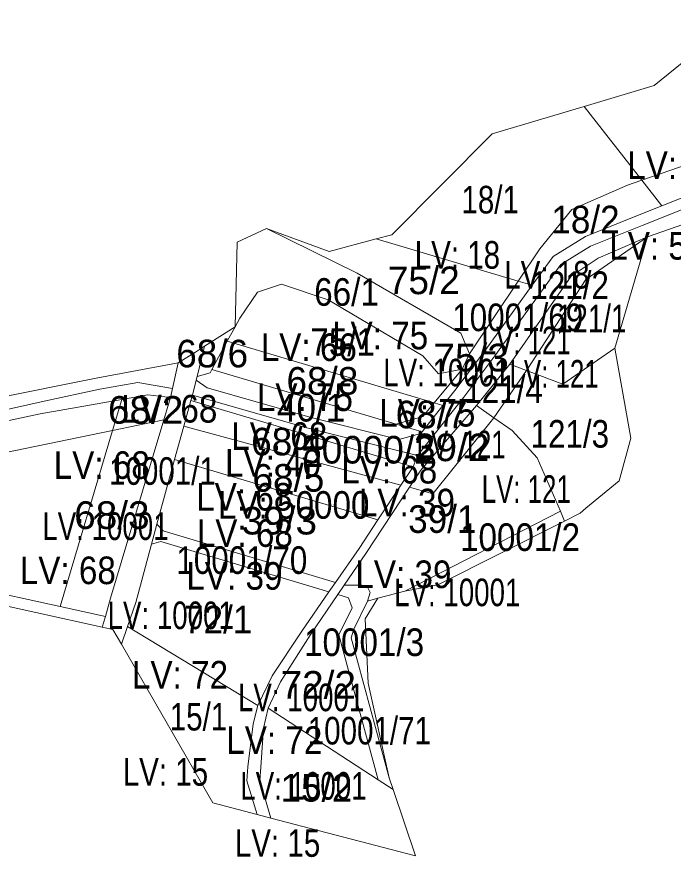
# Model space of a CAD drawing. Extents: x -713758 to -711119, y -1123067 to -1120789.
# Drawn here: x -713406.4 to -713168.6, y -1122325.9 to -1122021.5 of the extents above; entities that cross this region are included whole.
import ezdxf
from ezdxf.enums import TextEntityAlignment as Align

# ---------------------------------------------------------------- set-up
doc = ezdxf.new("R2010")
doc.units = 0
doc.header["$LTSCALE"] = 4
doc.layers.add('10', color=7, linetype='Continuous', lineweight=13)
doc.layers.add('11', color=7, linetype='Continuous')
doc.layers.add('13', color=7, linetype='Continuous')

msp = doc.modelspace()

# ---------------------------------------------------------------- linework, layer by layer
at = {"layer": '10'}
for points in [[(-713200.85, -1122053.94), (-713175.48, -1122046.35), (-713162.84, -1122036.08), (-713160.35, -1122039.4), (-713146.75, -1122034.59), (-713141.44, -1122029.61), (-713138.12, -1122034.76), (-713130.99, -1122030.94), (-713130.49, -1122024.8), (-713126.01, -1122031.6), (-713119.7, -1122021.46), (-713099.09, -1122050.28), (-713107.42, -1122053.38), (-713135.98, -1122065.38), (-713179.96, -1122080.66)], [(-713179.96, -1122080.66), (-713172.8, -1122089.95), (-713132.6, -1122073.85), (-713103.43, -1122061.72), (-713093.3, -1122058.22), (-713099.09, -1122050.28), (-713107.42, -1122053.38), (-713135.98, -1122065.38)], [(-713276.22, -1122101.91), (-713270.52, -1122100.4), (-713234.17, -1122063.9), (-713200.85, -1122053.94), (-713179.96, -1122080.66), (-713185.22, -1122082.48), (-713205.39, -1122091.27), (-713216.93, -1122105.54), (-713224.76, -1122117.22)], [(-713224.76, -1122117.22), (-713219.72, -1122118.72), (-713212.15, -1122108.25), (-713200.39, -1122101), (-713181.58, -1122093.48), (-713172.8, -1122089.95), (-713179.96, -1122080.66), (-713185.22, -1122082.48), (-713205.39, -1122091.27), (-713216.93, -1122105.54)], [(-713327.34, -1122133.82), (-713325.62, -1122130.68), (-713319.26, -1122121.21), (-713310.46, -1122118.36), (-713293.66, -1122124.01), (-713259.29, -1122144.32), (-713253.7, -1122150.79), (-713245.07, -1122149.07), (-713242.41, -1122143.56), (-713245.61, -1122136.04), (-713283.08, -1122114.33), (-713315.94, -1122098.12), (-713326.63, -1122103.08)], [(-713315.94, -1122098.12), (-713293.3, -1122106.44), (-713276.22, -1122101.91), (-713224.76, -1122117.22), (-713242.41, -1122143.56), (-713245.61, -1122136.04), (-713283.08, -1122114.33)], [(-713227.78, -1122147.31), (-713205.63, -1122115.4), (-713195.81, -1122108.91), (-713177.94, -1122101.13), (-713200.31, -1122116.67), (-713221.71, -1122149.59)], [(-713221.71, -1122149.59), (-713200.31, -1122116.67), (-713177.94, -1122101.13), (-713189.83, -1122141.53), (-713208.63, -1122154.49)], [(-713255.18, -1122161.34), (-713252.02, -1122162.28), (-713247.68, -1122156.81), (-713236.52, -1122141.96), (-713219.72, -1122118.72), (-713224.76, -1122117.22), (-713242.41, -1122143.56), (-713245.07, -1122149.07)], [(-713330.18, -1122139.02), (-713327.34, -1122133.82), (-713325.62, -1122130.68), (-713319.26, -1122121.21), (-713310.46, -1122118.36), (-713293.66, -1122124.01), (-713259.29, -1122144.32), (-713253.7, -1122150.79), (-713245.07, -1122149.07), (-713255.18, -1122161.34)], [(-713341.07, -1122151.74), (-713336.38, -1122150.38), (-713335.74, -1122149.21), (-713330.18, -1122139.02), (-713327.34, -1122133.82), (-713338.36, -1122140.8)], [(-713335.74, -1122149.21), (-713330.18, -1122139.02), (-713255.18, -1122161.34), (-713259.28, -1122166.31), (-713268.96, -1122169.08)], [(-713375.41, -1122242.51), (-713371.58, -1122243.35), (-713368.49, -1122248.72), (-713366.29, -1122242.33), (-713363.3, -1122233.65), (-713357.62, -1122212.53), (-713355.65, -1122205.21), (-713352.22, -1122192.45), (-713349.27, -1122181.82), (-713345.92, -1122169.75), (-713343.34, -1122160.48), (-713342.74, -1122158.5), (-713341.39, -1122153.06), (-713341.07, -1122151.74), (-713338.36, -1122140.8), (-713341.68, -1122142.9), (-713345.35, -1122145.22), (-713347.92, -1122146.85), (-713349.96, -1122156.15), (-713350.67, -1122159.31), (-713353.1, -1122167.47), (-713372.39, -1122232.08), (-713374.3, -1122238.66)], [(-713233.57, -1122166.7), (-713221.71, -1122149.59), (-713208.63, -1122154.49), (-713189.83, -1122141.53), (-713184, -1122174.1), (-713188.25, -1122189.5), (-713200.28, -1122199.51), (-713202.32, -1122201.29), (-713207.97, -1122204.13), (-713209.43, -1122200.56), (-713217.93, -1122181.24), (-713226.99, -1122171.38)], [(-713471.06, -1122176.68), (-713420.3, -1122165.95), (-713396.46, -1122160.64), (-713376.27, -1122156.29), (-713362.5, -1122153.91), (-713349.96, -1122156.15), (-713347.92, -1122146.85), (-713377.62, -1122152.32), (-713415.72, -1122159.97), (-713435.98, -1122165.29), (-713460.95, -1122160.94), (-713469.32, -1122159.14)], [(-713239.89, -1122162.21), (-713227.78, -1122147.31), (-713221.71, -1122149.59), (-713233.57, -1122166.7)], [(-713341.39, -1122153.06), (-713337.48, -1122155.85), (-713299.82, -1122166.66), (-713267.97, -1122174.55), (-713260.03, -1122172.37), (-713259.62, -1122171.86), (-713268.96, -1122169.08), (-713335.74, -1122149.21), (-713336.38, -1122150.38), (-713341.07, -1122151.74)], [(-713472.83, -1122194.45), (-713411, -1122179.39), (-713371.73, -1122171.3), (-713368.39, -1122160.09), (-713397.9, -1122165.24), (-713456.26, -1122177.73), (-713471.45, -1122180.61)], [(-713371.73, -1122171.3), (-713353.1, -1122167.47), (-713350.67, -1122159.31), (-713358.93, -1122158.44), (-713368.39, -1122160.09)], [(-713345.92, -1122169.75), (-713267.27, -1122191.11), (-713262.86, -1122184.43), (-713301.44, -1122172.89), (-713343.34, -1122160.48)], [(-713343.34, -1122160.48), (-713342.74, -1122158.5), (-713300.85, -1122170.53), (-713261.24, -1122180.34), (-713262.86, -1122184.43), (-713301.44, -1122172.89)], [(-713268.96, -1122169.08), (-713259.28, -1122166.31), (-713255.18, -1122161.34), (-713252.02, -1122162.28), (-713259.62, -1122171.86)], [(-713264.13, -1122191.89), (-713255.71, -1122194.31), (-713233.57, -1122166.7), (-713239.89, -1122162.21), (-713260.06, -1122185.75)], [(-713390.72, -1122235.07), (-713374.3, -1122238.66), (-713372.39, -1122232.08), (-713353.1, -1122167.47), (-713371.73, -1122171.3)], [(-713287.77, -1122227.3), (-713281.4, -1122227.39), (-713279.29, -1122228.27), (-713278.43, -1122230.03), (-713279.35, -1122233.09), (-713275.6, -1122232.08), (-713265.87, -1122229.47), (-713209.43, -1122200.56), (-713217.93, -1122181.24), (-713226.99, -1122171.38), (-713233.57, -1122166.7), (-713255.71, -1122194.31), (-713264.13, -1122191.89), (-713280, -1122215.83)], [(-713475.42, -1122220.51), (-713462.41, -1122220.52), (-713422.85, -1122228.06), (-713390.72, -1122235.07), (-713371.73, -1122171.3), (-713411, -1122179.39), (-713472.83, -1122194.45)], [(-713349.27, -1122181.82), (-713345.92, -1122169.75), (-713267.27, -1122191.11), (-713275.6, -1122203.73)], [(-713355.65, -1122205.21), (-713352.22, -1122192.45), (-713349.27, -1122181.82), (-713275.6, -1122203.73), (-713282.39, -1122214.01), (-713290.95, -1122226.34), (-713353.34, -1122207.63)], [(-713265.87, -1122229.47), (-713253.9, -1122227.22), (-713207.97, -1122204.13), (-713209.43, -1122200.56)], [(-713357.62, -1122212.53), (-713354.25, -1122211.53), (-713293.35, -1122229.79), (-713290.95, -1122226.34), (-713353.34, -1122207.63), (-713355.65, -1122205.21)], [(-713366.29, -1122242.33), (-713319.07, -1122270.98), (-713313.87, -1122260.23), (-713303.19, -1122243.97), (-713293.35, -1122229.79), (-713354.25, -1122211.53), (-713357.62, -1122212.53), (-713363.3, -1122233.65)], [(-713290.11, -1122230.74), (-713286.19, -1122231.92), (-713284.96, -1122235.53), (-713289.71, -1122245.4), (-713275.5, -1122297.87), (-713270.12, -1122301.38), (-713271.56, -1122297.12), (-713285.27, -1122246.48), (-713284.28, -1122243.34), (-713279.35, -1122233.09), (-713278.43, -1122230.03), (-713279.29, -1122228.27), (-713281.4, -1122227.39), (-713287.77, -1122227.3)], [(-713315.35, -1122271.91), (-713275.5, -1122297.87), (-713289.71, -1122245.4), (-713284.96, -1122235.53), (-713286.19, -1122231.92), (-713290.11, -1122230.74), (-713300.12, -1122245.52), (-713310.87, -1122262.42)], [(-713285.27, -1122246.48), (-713271.56, -1122297.12), (-713279.07, -1122262.87), (-713280.16, -1122239.53), (-713275.6, -1122232.08), (-713279.35, -1122233.09), (-713284.28, -1122243.34)], [(-713368.49, -1122248.72), (-713335.41, -1122306.22), (-713319.33, -1122310.43), (-713323.12, -1122298.26), (-713322.68, -1122293.19), (-713320.82, -1122277.56), (-713319.07, -1122270.98), (-713366.29, -1122242.33)], [(-713318.32, -1122298.13), (-713314.36, -1122311.73), (-713261.97, -1122325.43), (-713270.12, -1122301.38), (-713275.5, -1122297.87), (-713315.35, -1122271.91), (-713317.02, -1122279.18), (-713318.04, -1122293.27)]]:
    msp.add_lwpolyline(points, close=True, dxfattribs=at)
for points in [[(-713132.6, -1122073.85), (-713172.8, -1122089.95), (-713181.58, -1122093.48), (-713200.39, -1122101), (-713212.15, -1122108.25), (-713219.72, -1122118.72), (-713236.52, -1122141.96), (-713247.68, -1122156.81), (-713252.02, -1122162.28), (-713259.62, -1122171.86), (-713260.03, -1122172.37), (-713267.97, -1122174.55), (-713299.82, -1122166.66), (-713337.48, -1122155.85), (-713341.39, -1122153.06), (-713342.74, -1122158.5), (-713300.85, -1122170.53), (-713261.24, -1122180.34), (-713244.52, -1122159.26), (-713233.28, -1122144.31), (-713209.37, -1122111.24), (-713198.58, -1122104.58), (-713179.85, -1122097.09), (-713131.11, -1122077.56)], [(-713128.83, -1122084.07), (-713177.94, -1122101.13), (-713195.81, -1122108.91), (-713205.63, -1122115.4), (-713227.78, -1122147.31), (-713239.89, -1122162.21), (-713260.06, -1122185.75), (-713264.13, -1122191.89), (-713280, -1122215.83), (-713287.77, -1122227.3), (-713290.11, -1122230.74), (-713300.12, -1122245.52), (-713310.87, -1122262.42), (-713315.35, -1122271.91), (-713317.02, -1122279.18), (-713318.04, -1122293.27), (-713318.32, -1122298.13), (-713314.36, -1122311.73), (-713319.33, -1122310.43), (-713323.12, -1122298.26), (-713322.68, -1122293.19), (-713320.82, -1122277.56), (-713319.07, -1122270.98), (-713313.87, -1122260.23), (-713303.19, -1122243.97), (-713293.35, -1122229.79), (-713290.95, -1122226.34), (-713282.39, -1122214.01), (-713275.6, -1122203.73), (-713267.27, -1122191.11), (-713262.86, -1122184.43), (-713261.24, -1122180.34), (-713244.52, -1122159.26), (-713233.28, -1122144.31), (-713209.37, -1122111.24), (-713198.58, -1122104.58), (-713179.85, -1122097.09), (-713131.11, -1122077.56)], [(-713420.3, -1122165.95), (-713396.46, -1122160.64), (-713376.27, -1122156.29), (-713362.5, -1122153.91), (-713349.96, -1122156.15), (-713350.67, -1122159.31), (-713358.93, -1122158.44), (-713368.39, -1122160.09), (-713397.9, -1122165.24), (-713456.26, -1122177.73)], [(-713423.67, -1122231.97), (-713375.41, -1122242.51), (-713374.3, -1122238.66), (-713390.72, -1122235.07), (-713422.85, -1122228.06)]]:
    msp.add_lwpolyline(points, dxfattribs=at)

# ---------------------------------------------------------------- texts
at = {"layer": '11'}
for s, width, p in [('18/1', 0.8, (-713234.929, -1122092.7)), ('18/2', 0.95, (-713200.4, -1122099.89)), ('121/2', 0.85, (-713206.15, -1122123.7)), ('66/1', 0.9, (-713286.959, -1122126.14)), ('10001/69', 0.85, (-713224.961, -1122135.33)), ('121/1', 0.75, (-713198.15, -1122135.77)), ('75/1', 0.9, (-713288.35, -1122144.27)), ('75/3', 1.05, (-713241.841, -1122149.9)), ('121/4', 0.85, (-713230.081, -1122161.38)), ('68/2', 1.05, (-713359.73, -1122168.85)), ('40/1', 0.95, (-713299.79, -1122168.07)), ('121/3', 0.85, (-713206.079, -1122177.53)), ('39/2', 1.05, (-713248.87, -1122182.43)), ('10001/1', 0.8, (-713353.64, -1122191)), ('68/3', 1.05, (-713371.95, -1122206.98)), ('39/3', 1.05, (-713311.301, -1122208.99)), ('39/1', 0.95, (-713252.26, -1122208.41)), ('10001/2', 0.9, (-713224.111, -1122214.96)), ('10001/70', 0.85, (-713324.88, -1122223.28)), ('72/1', 0.95, (-713333.45, -1122244.8)), ('10001/3', 0.9, (-713280.6, -1122253.01)), ('72/2', 1.05, (-713297.189, -1122268.46)), ('15/1', 0.8, (-713340.59, -1122279.99)), ('10001/71', 0.8, (-713278.69, -1122285.06))]:
    msp.add_text(s, height=10, dxfattribs=dict(at, width=width)).set_placement(p, align=Align.CENTER)
for s, p in [('75/2', (-713258.98, -1122121.93)), ('68/6', (-713335.62, -1122148.45)), ('68/8', (-713295.691, -1122158.33)), ('68/7', (-713256.17, -1122170.52)), ('68/4', (-713308.48, -1122180.33)), ('50000/2', (-713279.22, -1122183.29)), ('68/5', (-713308.03, -1122193.48)), ('15/2', (-713297.87, -1122305.75))]:
    msp.add_text(s, height=10, dxfattribs=at).set_placement(p, align=Align.CENTER)
at = {"layer": '13'}
for s, width, p in [('LV: 66 ', 0.9, (-713166.226, -1122080.2)), ('LV: 50000 ', 0.9, (-713162.673, -1122109.42)), ('LV: 18 ', 0.8, (-713245.302, -1122112.7)), ('LV: 18 ', 0.8, (-713212.882, -1122119.89)), ('LV: 75 ', 0.9, (-713273.101, -1122141.93)), ('LV: 66 ', 0.9, (-713298.938, -1122146.14)), ('LV: 121 ', 0.7, (-713220.572, -1122143.7)), ('LV: 10001 ', 0.75, (-713249.386, -1122155.33)), ('LV: 121 ', 0.7, (-713210.464, -1122155.77)), ('LV: 75 ', 0.9, (-713300.361, -1122164.27)), ('LV: 68 ', 0.9, (-713349.473, -1122168.45)), ('LV: 75 ', 0.9, (-713256.027, -1122169.9)), ('LV: 68 ', 0.9, (-713309.645, -1122178.33)), ('LV: 121 ', 0.7, (-713244.134, -1122181.38)), ('LV: 68 ', 0.9, (-713373.951, -1122188.85)), ('LV: 40 ', 0.9, (-713311.902, -1122188.07)), ('LV: 68 ', 0.9, (-713269.823, -1122190.52)), ('LV: 121 ', 0.7, (-713220.568, -1122197.53)), ('LV: 68 ', 0.9, (-713322.333, -1122200.33)), ('LV: 50000 ', 0.9, (-713304.416, -1122203.29)), ('LV: 39 ', 0.9, (-713263.392, -1122202.43)), ('LV: 10001 ', 0.75, (-713372.88, -1122211)), ('LV: 68 ', 0.9, (-713322.118, -1122213.48)), ('LV: 68 ', 0.9, (-713386.238, -1122226.98)), ('LV: 39 ', 0.9, (-713264.674, -1122228.41)), ('LV: 39 ', 0.9, (-713325.89, -1122228.99)), ('LV: 10001 ', 0.75, (-713245.458, -1122234.96)), ('LV: 10001 ', 0.75, (-713349.239, -1122243.28)), ('LV: 72 ', 0.9, (-713345.596, -1122264.8)), ('LV: 10001 ', 0.75, (-713302.014, -1122273.01)), ('LV: 72 ', 0.9, (-713311.444, -1122288.46)), ('LV: 15 ', 0.8, (-713351.064, -1122299.99)), ('LV: 10001 ', 0.75, (-713301.175, -1122305.06)), ('LV: 15 ', 0.8, (-713310.453, -1122325.75))]:
    msp.add_text(s, height=10, dxfattribs=dict(at, width=width)).set_placement(p, align=Align.CENTER)

doc.saveas('drawing.dxf')
